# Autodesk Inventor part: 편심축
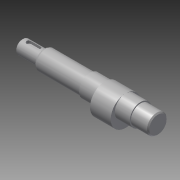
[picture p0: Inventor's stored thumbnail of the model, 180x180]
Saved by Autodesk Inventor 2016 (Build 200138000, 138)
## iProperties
Created: 2017-08
Part Number: 편심축
Material: 강철, 연강
Document SubType Name: Modeling
Designer: mduedu
Density: 1 g/cm^3
Appearance: 강철
Author: mduedu
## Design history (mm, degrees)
sketch "스케치1"
  geometry: L1 (0, 0)-(118, 0); L2 (118, 0)-(118, 8.5); L3 (118, 8.5)-(103, 8.5); L4 (103, 8.5)-(103, 9.5); L5 (103, 9.5)-(59, 9.5); L6 (59, 9.5)-(59, 8.5); L7 (59, 8.5)-(19, 8.5); L8 (19, 8.5)-(19, 6); L9 (19, 6)-(0, 6); L10 (0, 6)-(0, 0)
  constraints: 20 end point, 6 parallel, 2 collinear, 2 perpendicular, 1 horizontal
  dimensions: "d0" = 118 distance of L1.start L1.end; "d1" = 17 diameter of L3 L1; "d2" = 19 diameter of L5 L1; "d3" = 12 diameter of L9 L1; "d4" = 19 distance of L8.end L9.end; "d5" = 15 distance of L2.end L3.end; "d6" = 44 distance of L4.end L5.end
revolve "회전1" sketch "스케치1" stored, may be unused: angle "d7" = 90 deg
node "작업 평면1"
sketch "스케치2"
  geometry: C1 r 9.5 at (0, 0) reference; C2 r 13 at (0, -3.5); 1 further point
  constraints: 1 centre point, 1 tangent, 1 vertical alignment
  dimensions: "d8" = 3.5 distance of point (0, 0) C2.centre
extrude "돌출1" join sketch "스케치2" stored distance "d9" = 18; taper "d10" = 0 deg
chamfer "모따기1" distance "d11" = 1; stored, may be unused: second distance "d12" = 2, angle "d13" = 45 deg
node "작업 평면2"
sketch "스케치3"
  geometry: L1 (3.5, -2)-(-4.5, -2); L2 (-4.5, -2)-(-4.5, 2); L3 (-4.5, 2)-(3.5, 2); L4 (3.5, 2)-(3.5, -2); L5 (9.5, 6)-(9.5, -6) reference; A1 r 2 centre (3.5, 0) between (3.5, -2) and (3.5, 2); A2 r 2 centre (-4.5, 0) between (-4.5, 2) and (-4.5, -2); A3 r 2 centre (3.5, 0) between (3.5, 2) and (3.5, -2); A4 r 2 centre (-4.5, 0) between (-4.5, -2) and (-4.5, 2); 1 further point
  constraints: 8 end point, 8 point on circle, 4 centre point, 2 midpoint, 2 parallel, 1 horizontal, 1 horizontal alignment, 1 perpendicular
  dimensions: "d14" = 12 dimension on A2 A1; "d16" = 4 distance between parallel lines of L3 L1; "d17" = 4 distance edge to line of A1 L5
extrude "돌출2" cut sketch "스케치3" distance "d18" = 2.5; taper "d19" = 0 deg
chamfer "모따기2" distance "d20" = 1; stored, may be unused: second distance "d21" = 2, angle "d22" = 45 deg
chamfer "모따기3" distance "d23" = 1; stored, may be unused: second distance "d24" = 2, angle "d25" = 60 deg
fillet "모깎기1" dims "d26" = 0.5
hole "구멍1" diameter "d29" = 3.242; stored, may be unused: countersink angle "d33" = 90 deg, drill point angle "d35" = 118 deg; dims "d30" = 8, "d31" = 4, "d32" = 2, "d34" = 10, "d36" = 10, "d37" = 10
node "솔리드1"
node "절단 모서리 투영1"
